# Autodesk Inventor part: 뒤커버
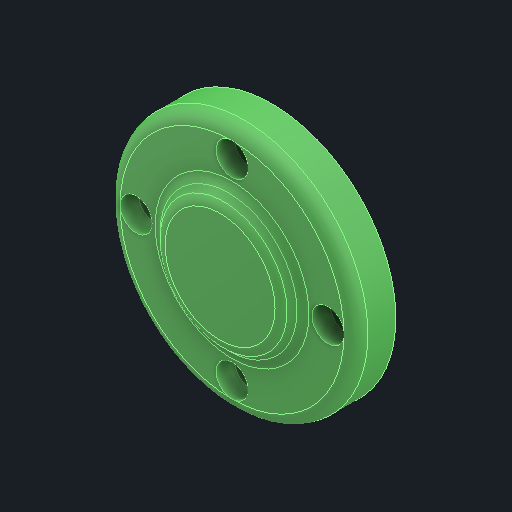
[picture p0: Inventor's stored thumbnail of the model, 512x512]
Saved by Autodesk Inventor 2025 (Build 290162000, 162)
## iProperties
Created: 2025-08
Part Number: 뒤커버
Material: 알루미늄 6061
Document SubType Name: Modeling
Designer: infra11
Density: 2.71 g/cm^3
Appearance: 기본값
Author: jhkim
Sending System: Autodesk Inventor 2026
Preprocessor: ST-DEVELOPER v20.1
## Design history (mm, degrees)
feature "솔리드1"
node "솔리드2"
